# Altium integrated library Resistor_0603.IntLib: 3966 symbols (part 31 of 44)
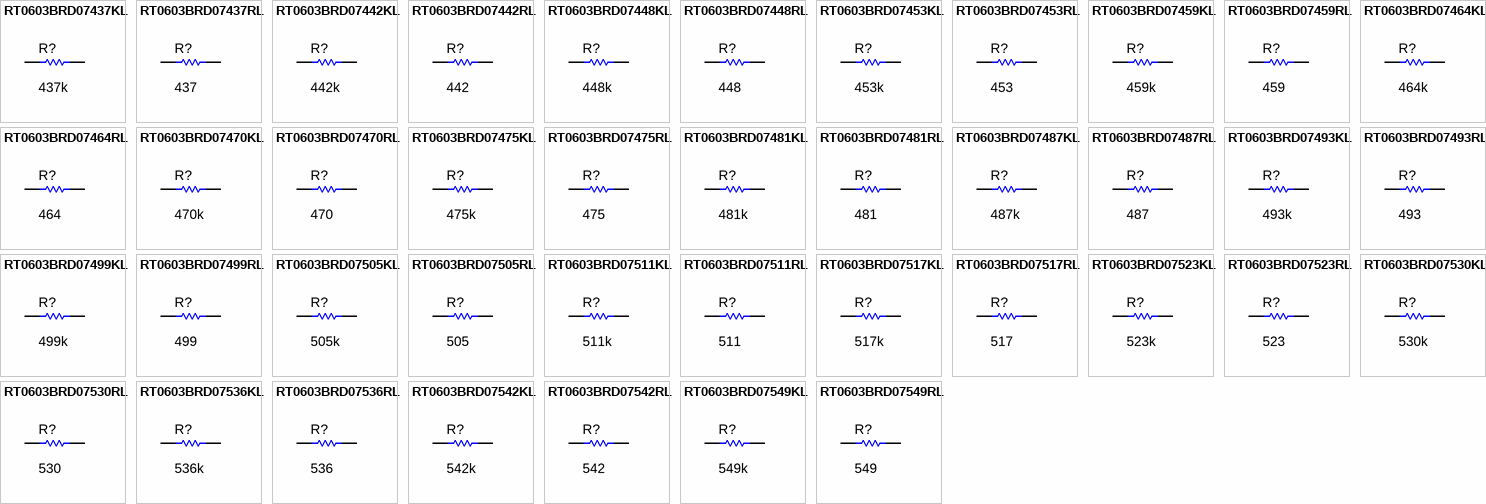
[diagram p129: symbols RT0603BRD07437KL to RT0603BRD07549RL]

## RT0603BRD07487KL
designator R?  ValueDisplayed: 487k  (hidden comment: RT0603BRD07487KL)
RES, 487 k, 0.1%, 0.1 W, 0603; Manufacturer: Yageo America; CompType: Resistor; Value: 487k; Res_ohm: 487000; Tolerance_%: 0.1; Value2: 0.1W; VDC_V: 75; TempCo: 25 ppm/C; SizeArea_mm2: 1.28; SizeX_mm: 1.6; SizeY_mm: 0.8; SizeZ_mm: 1; EIA_Code: E192; U/M: EA; AEC Category: Q200
signal-integrity model Resistor
simulation model Resistor
footprint 0603
footprint 0603M
footprint 0603L
footprint 0603_HV
footprint 0603S
pins: 1, 2

## RT0603BRD07487RL
designator R?  ValueDisplayed: 487  (hidden comment: RT0603BRD07487RL)
RES, 487, 0.1%, 0.1 W, 0603; Manufacturer: Yageo America; CompType: Resistor; Value: 487; Value_Code: 487R; Tolerance_%: 0.1; Value2: 0.1W; VDC_V: 75; TempCo: 25 ppm/C; SizeArea_mm2: 1.28; SizeX_mm: 1.6; SizeY_mm: 0.8; SizeZ_mm: 1; EIA_Code: E192; U/M: EA; AEC Category: Q200
signal-integrity model Resistor
simulation model Resistor
footprint 0603
footprint 0603M
footprint 0603L
footprint 0603_HV
footprint 0603S
pins: 1, 2

## RT0603BRD07493KL
designator R?  ValueDisplayed: 493k  (hidden comment: RT0603BRD07493KL)
RES, 493 k, 0.1%, 0.1 W, 0603; Manufacturer: Yageo America; CompType: Resistor; Value: 493k; Res_ohm: 493000; Tolerance_%: 0.1; Value2: 0.1W; VDC_V: 75; TempCo: 25 ppm/C; SizeArea_mm2: 1.28; SizeX_mm: 1.6; SizeY_mm: 0.8; SizeZ_mm: 1; EIA_Code: E192; U/M: EA; AEC Category: Q200
signal-integrity model Resistor
simulation model Resistor
footprint 0603
footprint 0603M
footprint 0603L
footprint 0603_HV
footprint 0603S
pins: 1, 2

## RT0603BRD07493RL
designator R?  ValueDisplayed: 493  (hidden comment: RT0603BRD07493RL)
RES, 493, 0.1%, 0.1 W, 0603; Manufacturer: Yageo America; CompType: Resistor; Value: 493; Value_Code: 493R; Tolerance_%: 0.1; Value2: 0.1W; VDC_V: 75; TempCo: 25 ppm/C; SizeArea_mm2: 1.28; SizeX_mm: 1.6; SizeY_mm: 0.8; SizeZ_mm: 1; EIA_Code: E192; U/M: EA; AEC Category: Q200
signal-integrity model Resistor
simulation model Resistor
footprint 0603
footprint 0603M
footprint 0603L
footprint 0603_HV
footprint 0603S
pins: 1, 2

## RT0603BRD07499KL
designator R?  ValueDisplayed: 499k  (hidden comment: RT0603BRD07499KL)
RES, 499 k, 0.1%, 0.1 W, 0603; Manufacturer: Yageo America; CompType: Resistor; Value: 499k; Res_ohm: 499000; Tolerance_%: 0.1; Value2: 0.1W; VDC_V: 75; TempCo: 25 ppm/C; SizeArea_mm2: 1.28; SizeX_mm: 1.6; SizeY_mm: 0.8; SizeZ_mm: 1; EIA_Code: E192; U/M: EA; AEC Category: Q200; Green_Lifecycle: Active; Green_REACh: Passed
signal-integrity model Resistor
simulation model Resistor
footprint 0603
footprint 0603M
footprint 0603L
footprint 0603_HV
footprint 0603S
pins: 1, 2

## RT0603BRD07499RL
designator R?  ValueDisplayed: 499  (hidden comment: RT0603BRD07499RL)
RES, 499, 0.1%, 0.1 W, 0603; Manufacturer: Yageo America; CompType: Resistor; Value: 499; Value_Code: 499R; Tolerance_%: 0.1; Value2: 0.1W; VDC_V: 75; TempCo: 25 ppm/C; SizeArea_mm2: 1.28; SizeX_mm: 1.6; SizeY_mm: 0.8; SizeZ_mm: 1; EIA_Code: E192; U/M: EA; AEC Category: Q200
signal-integrity model Resistor
simulation model Resistor
footprint 0603
footprint 0603M
footprint 0603L
footprint 0603_HV
footprint 0603S
pins: 1, 2

## RT0603BRD07505KL
designator R?  ValueDisplayed: 505k  (hidden comment: RT0603BRD07505KL)
RES, 505 k, 0.1%, 0.1 W, 0603; Manufacturer: Yageo America; CompType: Resistor; Value: 505k; Res_ohm: 505000; Tolerance_%: 0.1; Value2: 0.1W; VDC_V: 75; TempCo: 25 ppm/C; SizeArea_mm2: 1.28; SizeX_mm: 1.6; SizeY_mm: 0.8; SizeZ_mm: 1; EIA_Code: E192; U/M: EA; AEC Category: Q200
signal-integrity model Resistor
simulation model Resistor
footprint 0603
footprint 0603M
footprint 0603L
footprint 0603_HV
footprint 0603S
pins: 1, 2

## RT0603BRD07505RL
designator R?  ValueDisplayed: 505  (hidden comment: RT0603BRD07505RL)
RES, 505, 0.1%, 0.1 W, 0603; Manufacturer: Yageo America; CompType: Resistor; Value: 505; Value_Code: 505R; Tolerance_%: 0.1; Value2: 0.1W; VDC_V: 75; TempCo: 25 ppm/C; SizeArea_mm2: 1.28; SizeX_mm: 1.6; SizeY_mm: 0.8; SizeZ_mm: 1; EIA_Code: E192; U/M: EA; AEC Category: Q200
signal-integrity model Resistor
simulation model Resistor
footprint 0603
footprint 0603M
footprint 0603L
footprint 0603_HV
footprint 0603S
pins: 1, 2

## RT0603BRD07511KL
designator R?  ValueDisplayed: 511k  (hidden comment: RT0603BRD07511KL)
RES, 511 k, 0.1%, 0.1 W, 0603; Manufacturer: Yageo America; CompType: Resistor; Value: 511k; Res_ohm: 511000; Tolerance_%: 0.1; Value2: 0.1W; VDC_V: 75; TempCo: 25 ppm/C; SizeArea_mm2: 1.28; SizeX_mm: 1.6; SizeY_mm: 0.8; SizeZ_mm: 1; EIA_Code: E192; U/M: EA; AEC Category: Q200
signal-integrity model Resistor
simulation model Resistor
footprint 0603
footprint 0603M
footprint 0603L
footprint 0603_HV
footprint 0603S
pins: 1, 2

## RT0603BRD07511RL
designator R?  ValueDisplayed: 511  (hidden comment: RT0603BRD07511RL)
RES, 511, 0.1%, 0.1 W, 0603; Manufacturer: Yageo America; CompType: Resistor; Value: 511; Value_Code: 511R; Tolerance_%: 0.1; Value2: 0.1W; VDC_V: 75; TempCo: 25 ppm/C; SizeArea_mm2: 1.28; SizeX_mm: 1.6; SizeY_mm: 0.8; SizeZ_mm: 1; EIA_Code: E192; U/M: EA; AEC Category: Q200
signal-integrity model Resistor
simulation model Resistor
footprint 0603
footprint 0603M
footprint 0603L
footprint 0603_HV
footprint 0603S
pins: 1, 2

## RT0603BRD07517KL
designator R?  ValueDisplayed: 517k  (hidden comment: RT0603BRD07517KL)
RES, 517 k, 0.1%, 0.1 W, 0603; Manufacturer: Yageo America; CompType: Resistor; Value: 517k; Res_ohm: 517000; Tolerance_%: 0.1; Value2: 0.1W; VDC_V: 75; TempCo: 25 ppm/C; SizeArea_mm2: 1.28; SizeX_mm: 1.6; SizeY_mm: 0.8; SizeZ_mm: 1; EIA_Code: E192; U/M: EA; AEC Category: Q200
signal-integrity model Resistor
simulation model Resistor
footprint 0603
footprint 0603M
footprint 0603L
footprint 0603_HV
footprint 0603S
pins: 1, 2

## RT0603BRD07517RL
designator R?  ValueDisplayed: 517  (hidden comment: RT0603BRD07517RL)
RES, 517, 0.1%, 0.1 W, 0603; Manufacturer: Yageo America; CompType: Resistor; Value: 517; Value_Code: 517R; Tolerance_%: 0.1; Value2: 0.1W; VDC_V: 75; TempCo: 25 ppm/C; SizeArea_mm2: 1.28; SizeX_mm: 1.6; SizeY_mm: 0.8; SizeZ_mm: 1; EIA_Code: E192; U/M: EA; AEC Category: Q200
signal-integrity model Resistor
simulation model Resistor
footprint 0603
footprint 0603M
footprint 0603L
footprint 0603_HV
footprint 0603S
pins: 1, 2

## RT0603BRD07523KL
designator R?  ValueDisplayed: 523k  (hidden comment: RT0603BRD07523KL)
RES, 523 k, 0.1%, 0.1 W, 0603; Manufacturer: Yageo America; CompType: Resistor; Value: 523k; Res_ohm: 523000; Tolerance_%: 0.1; Value2: 0.1W; VDC_V: 75; TempCo: 25 ppm/C; SizeArea_mm2: 1.28; SizeX_mm: 1.6; SizeY_mm: 0.8; SizeZ_mm: 1; EIA_Code: E192; U/M: EA; AEC Category: Q200
signal-integrity model Resistor
simulation model Resistor
footprint 0603
footprint 0603M
footprint 0603L
footprint 0603_HV
footprint 0603S
pins: 1, 2

## RT0603BRD07523RL
designator R?  ValueDisplayed: 523  (hidden comment: RT0603BRD07523RL)
RES, 523, 0.1%, 0.1 W, 0603; Manufacturer: Yageo America; CompType: Resistor; Value: 523; Value_Code: 523R; Tolerance_%: 0.1; Value2: 0.1W; VDC_V: 75; TempCo: 25 ppm/C; SizeArea_mm2: 1.28; SizeX_mm: 1.6; SizeY_mm: 0.8; SizeZ_mm: 1; EIA_Code: E192; U/M: EA; AEC Category: Q200
signal-integrity model Resistor
simulation model Resistor
footprint 0603
footprint 0603M
footprint 0603L
footprint 0603_HV
footprint 0603S
pins: 1, 2

## RT0603BRD07530KL
designator R?  ValueDisplayed: 530k  (hidden comment: RT0603BRD07530KL)
RES, 530 k, 0.1%, 0.1 W, 0603; Manufacturer: Yageo America; CompType: Resistor; Value: 530k; Res_ohm: 530000; Tolerance_%: 0.1; Value2: 0.1W; VDC_V: 75; TempCo: 25 ppm/C; SizeArea_mm2: 1.28; SizeX_mm: 1.6; SizeY_mm: 0.8; SizeZ_mm: 1; EIA_Code: E192; U/M: EA; AEC Category: Q200
signal-integrity model Resistor
simulation model Resistor
footprint 0603
footprint 0603M
footprint 0603L
footprint 0603_HV
footprint 0603S
pins: 1, 2

## RT0603BRD07530RL
designator R?  ValueDisplayed: 530  (hidden comment: RT0603BRD07530RL)
RES, 530, 0.1%, 0.1 W, 0603; Manufacturer: Yageo America; CompType: Resistor; Value: 530; Value_Code: 530R; Tolerance_%: 0.1; Value2: 0.1W; VDC_V: 75; TempCo: 25 ppm/C; SizeArea_mm2: 1.28; SizeX_mm: 1.6; SizeY_mm: 0.8; SizeZ_mm: 1; EIA_Code: E192; U/M: EA; AEC Category: Q200
signal-integrity model Resistor
simulation model Resistor
footprint 0603
footprint 0603M
footprint 0603L
footprint 0603_HV
footprint 0603S
pins: 1, 2

## RT0603BRD07536KL
designator R?  ValueDisplayed: 536k  (hidden comment: RT0603BRD07536KL)
RES, 536 k, 0.1%, 0.1 W, 0603; Manufacturer: Yageo America; CompType: Resistor; Value: 536k; Res_ohm: 536000; Tolerance_%: 0.1; Value2: 0.1W; VDC_V: 75; TempCo: 25 ppm/C; SizeArea_mm2: 1.28; SizeX_mm: 1.6; SizeY_mm: 0.8; SizeZ_mm: 1; EIA_Code: E192; U/M: EA; AEC Category: Q200
signal-integrity model Resistor
simulation model Resistor
footprint 0603
footprint 0603M
footprint 0603L
footprint 0603_HV
footprint 0603S
pins: 1, 2

## RT0603BRD07536RL
designator R?  ValueDisplayed: 536  (hidden comment: RT0603BRD07536RL)
RES, 536, 0.1%, 0.1 W, 0603; Manufacturer: Yageo America; CompType: Resistor; Value: 536; Value_Code: 536R; Tolerance_%: 0.1; Value2: 0.1W; VDC_V: 75; TempCo: 25 ppm/C; SizeArea_mm2: 1.28; SizeX_mm: 1.6; SizeY_mm: 0.8; SizeZ_mm: 1; EIA_Code: E192; U/M: EA; AEC Category: Q200
signal-integrity model Resistor
simulation model Resistor
footprint 0603
footprint 0603M
footprint 0603L
footprint 0603_HV
footprint 0603S
pins: 1, 2

## RT0603BRD07542KL
designator R?  ValueDisplayed: 542k  (hidden comment: RT0603BRD07542KL)
RES, 542 k, 0.1%, 0.1 W, 0603; Manufacturer: Yageo America; CompType: Resistor; Value: 542k; Res_ohm: 542000; Tolerance_%: 0.1; Value2: 0.1W; VDC_V: 75; TempCo: 25 ppm/C; SizeArea_mm2: 1.28; SizeX_mm: 1.6; SizeY_mm: 0.8; SizeZ_mm: 1; EIA_Code: E192; U/M: EA; AEC Category: Q200
signal-integrity model Resistor
simulation model Resistor
footprint 0603
footprint 0603M
footprint 0603L
footprint 0603_HV
footprint 0603S
pins: 1, 2

## RT0603BRD07542RL
designator R?  ValueDisplayed: 542  (hidden comment: RT0603BRD07542RL)
RES, 542, 0.1%, 0.1 W, 0603; Manufacturer: Yageo America; CompType: Resistor; Value: 542; Value_Code: 542R; Tolerance_%: 0.1; Value2: 0.1W; VDC_V: 75; TempCo: 25 ppm/C; SizeArea_mm2: 1.28; SizeX_mm: 1.6; SizeY_mm: 0.8; SizeZ_mm: 1; EIA_Code: E192; U/M: EA; AEC Category: Q200
signal-integrity model Resistor
simulation model Resistor
footprint 0603
footprint 0603M
footprint 0603L
footprint 0603_HV
footprint 0603S
pins: 1, 2

## RT0603BRD07549KL
designator R?  ValueDisplayed: 549k  (hidden comment: RT0603BRD07549KL)
RES, 549 k, 0.1%, 0.1 W, 0603; Manufacturer: Yageo America; CompType: Resistor; Value: 549k; Res_ohm: 549000; Tolerance_%: 0.1; Value2: 0.1W; VDC_V: 75; TempCo: 25 ppm/C; SizeArea_mm2: 1.28; SizeX_mm: 1.6; SizeY_mm: 0.8; SizeZ_mm: 1; EIA_Code: E192; U/M: EA; AEC Category: Q200
signal-integrity model Resistor
simulation model Resistor
footprint 0603
footprint 0603M
footprint 0603L
footprint 0603_HV
footprint 0603S
pins: 1, 2

## RT0603BRD07549RL
designator R?  ValueDisplayed: 549  (hidden comment: RT0603BRD07549RL)
RES, 549, 0.1%, 0.1 W, 0603; Manufacturer: Yageo America; CompType: Resistor; Value: 549; Value_Code: 549R; Tolerance_%: 0.1; Value2: 0.1W; VDC_V: 75; TempCo: 25 ppm/C; SizeArea_mm2: 1.28; SizeX_mm: 1.6; SizeY_mm: 0.8; SizeZ_mm: 1; EIA_Code: E192; U/M: EA; AEC Category: Q200
signal-integrity model Resistor
simulation model Resistor
footprint 0603
footprint 0603M
footprint 0603L
footprint 0603_HV
footprint 0603S
pins: 1, 2

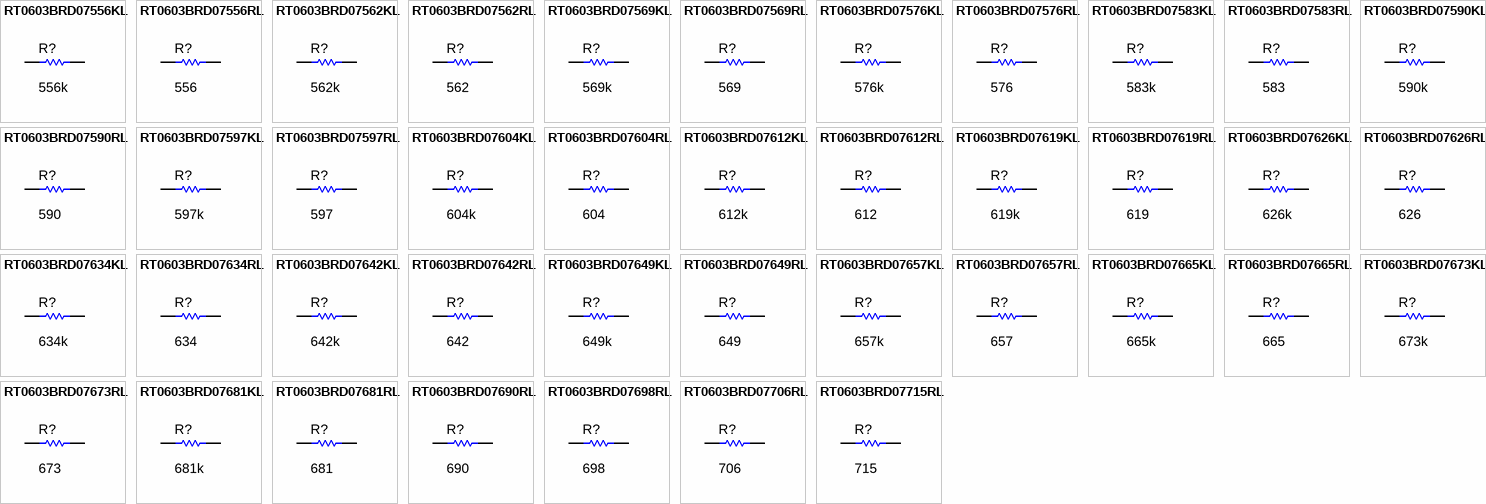
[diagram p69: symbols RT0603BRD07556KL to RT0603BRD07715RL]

## RT0603BRD07556KL
designator R?  ValueDisplayed: 556k  (hidden comment: RT0603BRD07556KL)
RES, 556 k, 0.1%, 0.1 W, 0603; Manufacturer: Yageo America; CompType: Resistor; Value: 556k; Res_ohm: 556000; Tolerance_%: 0.1; Value2: 0.1W; VDC_V: 75; TempCo: 25 ppm/C; SizeArea_mm2: 1.28; SizeX_mm: 1.6; SizeY_mm: 0.8; SizeZ_mm: 1; EIA_Code: E192; U/M: EA; AEC Category: Q200
signal-integrity model Resistor
simulation model Resistor
footprint 0603
footprint 0603M
footprint 0603L
footprint 0603_HV
footprint 0603S
pins: 1, 2

## RT0603BRD07556RL
designator R?  ValueDisplayed: 556  (hidden comment: RT0603BRD07556RL)
RES, 556, 0.1%, 0.1 W, 0603; Manufacturer: Yageo America; CompType: Resistor; Value: 556; Value_Code: 556R; Tolerance_%: 0.1; Value2: 0.1W; VDC_V: 75; TempCo: 25 ppm/C; SizeArea_mm2: 1.28; SizeX_mm: 1.6; SizeY_mm: 0.8; SizeZ_mm: 1; EIA_Code: E192; U/M: EA; AEC Category: Q200
signal-integrity model Resistor
simulation model Resistor
footprint 0603
footprint 0603M
footprint 0603L
footprint 0603_HV
footprint 0603S
pins: 1, 2

## RT0603BRD07562KL
designator R?  ValueDisplayed: 562k  (hidden comment: RT0603BRD07562KL)
RES, 562 k, 0.1%, 0.1 W, 0603; Manufacturer: Yageo America; CompType: Resistor; Value: 562k; Res_ohm: 562000; Tolerance_%: 0.1; Value2: 0.1W; VDC_V: 75; TempCo: 25 ppm/C; SizeArea_mm2: 1.28; SizeX_mm: 1.6; SizeY_mm: 0.8; SizeZ_mm: 1; EIA_Code: E192; U/M: EA; AEC Category: Q200
signal-integrity model Resistor
simulation model Resistor
footprint 0603
footprint 0603M
footprint 0603L
footprint 0603_HV
footprint 0603S
pins: 1, 2

## RT0603BRD07562RL
designator R?  ValueDisplayed: 562  (hidden comment: RT0603BRD07562RL)
RES, 562, 0.1%, 0.1 W, 0603; Manufacturer: Yageo America; CompType: Resistor; Value: 562; Value_Code: 562R; Tolerance_%: 0.1; Value2: 0.1W; VDC_V: 75; TempCo: 25 ppm/C; SizeArea_mm2: 1.28; SizeX_mm: 1.6; SizeY_mm: 0.8; SizeZ_mm: 1; EIA_Code: E192; U/M: EA; AEC Category: Q200
signal-integrity model Resistor
simulation model Resistor
footprint 0603
footprint 0603M
footprint 0603L
footprint 0603_HV
footprint 0603S
pins: 1, 2

## RT0603BRD07569KL
designator R?  ValueDisplayed: 569k  (hidden comment: RT0603BRD07569KL)
RES, 569 k, 0.1%, 0.1 W, 0603; Manufacturer: Yageo America; CompType: Resistor; Value: 569k; Res_ohm: 569000; Tolerance_%: 0.1; Value2: 0.1W; VDC_V: 75; TempCo: 25 ppm/C; SizeArea_mm2: 1.28; SizeX_mm: 1.6; SizeY_mm: 0.8; SizeZ_mm: 1; EIA_Code: E192; U/M: EA; AEC Category: Q200
signal-integrity model Resistor
simulation model Resistor
footprint 0603
footprint 0603M
footprint 0603L
footprint 0603_HV
footprint 0603S
pins: 1, 2

## RT0603BRD07569RL
designator R?  ValueDisplayed: 569  (hidden comment: RT0603BRD07569RL)
RES, 569, 0.1%, 0.1 W, 0603; Manufacturer: Yageo America; CompType: Resistor; Value: 569; Value_Code: 569R; Tolerance_%: 0.1; Value2: 0.1W; VDC_V: 75; TempCo: 25 ppm/C; SizeArea_mm2: 1.28; SizeX_mm: 1.6; SizeY_mm: 0.8; SizeZ_mm: 1; EIA_Code: E192; U/M: EA; AEC Category: Q200
signal-integrity model Resistor
simulation model Resistor
footprint 0603
footprint 0603M
footprint 0603L
footprint 0603_HV
footprint 0603S
pins: 1, 2

## RT0603BRD07576KL
designator R?  ValueDisplayed: 576k  (hidden comment: RT0603BRD07576KL)
RES, 576 k, 0.1%, 0.1 W, 0603; Manufacturer: Yageo America; CompType: Resistor; Value: 576k; Res_ohm: 576000; Tolerance_%: 0.1; Value2: 0.1W; VDC_V: 75; TempCo: 25 ppm/C; SizeArea_mm2: 1.28; SizeX_mm: 1.6; SizeY_mm: 0.8; SizeZ_mm: 1; EIA_Code: E192; U/M: EA; AEC Category: Q200
signal-integrity model Resistor
simulation model Resistor
footprint 0603
footprint 0603M
footprint 0603L
footprint 0603_HV
footprint 0603S
pins: 1, 2

## RT0603BRD07576RL
designator R?  ValueDisplayed: 576  (hidden comment: RT0603BRD07576RL)
RES, 576, 0.1%, 0.1 W, 0603; Manufacturer: Yageo America; CompType: Resistor; Value: 576; Value_Code: 576R; Tolerance_%: 0.1; Value2: 0.1W; VDC_V: 75; TempCo: 25 ppm/C; SizeArea_mm2: 1.28; SizeX_mm: 1.6; SizeY_mm: 0.8; SizeZ_mm: 1; EIA_Code: E192; U/M: EA; AEC Category: Q200
signal-integrity model Resistor
simulation model Resistor
footprint 0603
footprint 0603M
footprint 0603L
footprint 0603_HV
footprint 0603S
pins: 1, 2

## RT0603BRD07583KL
designator R?  ValueDisplayed: 583k  (hidden comment: RT0603BRD07583KL)
RES, 583 k, 0.1%, 0.1 W, 0603; Manufacturer: Yageo America; CompType: Resistor; Value: 583k; Res_ohm: 583000; Tolerance_%: 0.1; Value2: 0.1W; VDC_V: 75; TempCo: 25 ppm/C; SizeArea_mm2: 1.28; SizeX_mm: 1.6; SizeY_mm: 0.8; SizeZ_mm: 1; EIA_Code: E192; U/M: EA; AEC Category: Q200
signal-integrity model Resistor
simulation model Resistor
footprint 0603
footprint 0603M
footprint 0603L
footprint 0603_HV
footprint 0603S
pins: 1, 2

## RT0603BRD07583RL
designator R?  ValueDisplayed: 583  (hidden comment: RT0603BRD07583RL)
RES, 583, 0.1%, 0.1 W, 0603; Manufacturer: Yageo America; CompType: Resistor; Value: 583; Value_Code: 583R; Tolerance_%: 0.1; Value2: 0.1W; VDC_V: 75; TempCo: 25 ppm/C; SizeArea_mm2: 1.28; SizeX_mm: 1.6; SizeY_mm: 0.8; SizeZ_mm: 1; EIA_Code: E192; U/M: EA; AEC Category: Q200
signal-integrity model Resistor
simulation model Resistor
footprint 0603
footprint 0603M
footprint 0603L
footprint 0603_HV
footprint 0603S
pins: 1, 2

## RT0603BRD07590KL
designator R?  ValueDisplayed: 590k  (hidden comment: RT0603BRD07590KL)
RES, 590 k, 0.1%, 0.1 W, 0603; Manufacturer: Yageo America; CompType: Resistor; Value: 590k; Res_ohm: 590000; Tolerance_%: 0.1; Value2: 0.1W; VDC_V: 75; TempCo: 25 ppm/C; SizeArea_mm2: 1.28; SizeX_mm: 1.6; SizeY_mm: 0.8; SizeZ_mm: 1; EIA_Code: E192; U/M: EA; AEC Category: Q200
signal-integrity model Resistor
simulation model Resistor
footprint 0603
footprint 0603M
footprint 0603L
footprint 0603_HV
footprint 0603S
pins: 1, 2

## RT0603BRD07590RL
designator R?  ValueDisplayed: 590  (hidden comment: RT0603BRD07590RL)
RES, 590, 0.1%, 0.1 W, 0603; Manufacturer: Yageo America; CompType: Resistor; Value: 590; Value_Code: 590R; Tolerance_%: 0.1; Value2: 0.1W; VDC_V: 75; TempCo: 25 ppm/C; SizeArea_mm2: 1.28; SizeX_mm: 1.6; SizeY_mm: 0.8; SizeZ_mm: 1; EIA_Code: E192; U/M: EA; AEC Category: Q200
signal-integrity model Resistor
simulation model Resistor
footprint 0603
footprint 0603M
footprint 0603L
footprint 0603_HV
footprint 0603S
pins: 1, 2

## RT0603BRD07597KL
designator R?  ValueDisplayed: 597k  (hidden comment: RT0603BRD07597KL)
RES, 597 k, 0.1%, 0.1 W, 0603; Manufacturer: Yageo America; CompType: Resistor; Value: 597k; Res_ohm: 597000; Tolerance_%: 0.1; Value2: 0.1W; VDC_V: 75; TempCo: 25 ppm/C; SizeArea_mm2: 1.28; SizeX_mm: 1.6; SizeY_mm: 0.8; SizeZ_mm: 1; EIA_Code: E192; U/M: EA; AEC Category: Q200
signal-integrity model Resistor
simulation model Resistor
footprint 0603
footprint 0603M
footprint 0603L
footprint 0603_HV
footprint 0603S
pins: 1, 2

## RT0603BRD07597RL
designator R?  ValueDisplayed: 597  (hidden comment: RT0603BRD07597RL)
RES, 597, 0.1%, 0.1 W, 0603; Manufacturer: Yageo America; CompType: Resistor; Value: 597; Value_Code: 597R; Tolerance_%: 0.1; Value2: 0.1W; VDC_V: 75; TempCo: 25 ppm/C; SizeArea_mm2: 1.28; SizeX_mm: 1.6; SizeY_mm: 0.8; SizeZ_mm: 1; EIA_Code: E192; U/M: EA; AEC Category: Q200
signal-integrity model Resistor
simulation model Resistor
footprint 0603
footprint 0603M
footprint 0603L
footprint 0603_HV
footprint 0603S
pins: 1, 2

## RT0603BRD07604KL
designator R?  ValueDisplayed: 604k  (hidden comment: RT0603BRD07604KL)
RES, 604 k, 0.1%, 0.1 W, 0603; Manufacturer: Yageo America; CompType: Resistor; Value: 604k; Res_ohm: 604000; Tolerance_%: 0.1; Value2: 0.1W; VDC_V: 75; TempCo: 25 ppm/C; SizeArea_mm2: 1.28; SizeX_mm: 1.6; SizeY_mm: 0.8; SizeZ_mm: 1; EIA_Code: E192; U/M: EA; AEC Category: Q200
signal-integrity model Resistor
simulation model Resistor
footprint 0603
footprint 0603M
footprint 0603L
footprint 0603_HV
footprint 0603S
pins: 1, 2

## RT0603BRD07604RL
designator R?  ValueDisplayed: 604  (hidden comment: RT0603BRD07604RL)
RES, 604, 0.1%, 0.1 W, 0603; Manufacturer: Yageo America; CompType: Resistor; Value: 604; Value_Code: 604R; Tolerance_%: 0.1; Value2: 0.1W; VDC_V: 75; TempCo: 25 ppm/C; SizeArea_mm2: 1.28; SizeX_mm: 1.6; SizeY_mm: 0.8; SizeZ_mm: 1; EIA_Code: E192; U/M: EA; AEC Category: Q200
signal-integrity model Resistor
simulation model Resistor
footprint 0603
footprint 0603M
footprint 0603L
footprint 0603_HV
footprint 0603S
pins: 1, 2

## RT0603BRD07612KL
designator R?  ValueDisplayed: 612k  (hidden comment: RT0603BRD07612KL)
RES, 612 k, 0.1%, 0.1 W, 0603; Manufacturer: Yageo America; CompType: Resistor; Value: 612k; Res_ohm: 612000; Tolerance_%: 0.1; Value2: 0.1W; VDC_V: 75; TempCo: 25 ppm/C; SizeArea_mm2: 1.28; SizeX_mm: 1.6; SizeY_mm: 0.8; SizeZ_mm: 1; EIA_Code: E192; U/M: EA; AEC Category: Q200
signal-integrity model Resistor
simulation model Resistor
footprint 0603
footprint 0603M
footprint 0603L
footprint 0603_HV
footprint 0603S
pins: 1, 2

## RT0603BRD07612RL
designator R?  ValueDisplayed: 612  (hidden comment: RT0603BRD07612RL)
RES, 612, 0.1%, 0.1 W, 0603; Manufacturer: Yageo America; CompType: Resistor; Value: 612; Value_Code: 612R; Tolerance_%: 0.1; Value2: 0.1W; VDC_V: 75; TempCo: 25 ppm/C; SizeArea_mm2: 1.28; SizeX_mm: 1.6; SizeY_mm: 0.8; SizeZ_mm: 1; EIA_Code: E192; U/M: EA; AEC Category: Q200
signal-integrity model Resistor
simulation model Resistor
footprint 0603
footprint 0603M
footprint 0603L
footprint 0603_HV
footprint 0603S
pins: 1, 2

## RT0603BRD07619KL
designator R?  ValueDisplayed: 619k  (hidden comment: RT0603BRD07619KL)
RES, 619 k, 0.1%, 0.1 W, 0603; Manufacturer: Yageo America; CompType: Resistor; Value: 619k; Res_ohm: 619000; Tolerance_%: 0.1; Value2: 0.1W; VDC_V: 75; TempCo: 25 ppm/C; SizeArea_mm2: 1.28; SizeX_mm: 1.6; SizeY_mm: 0.8; SizeZ_mm: 1; EIA_Code: E192; U/M: EA; AEC Category: Q200
signal-integrity model Resistor
simulation model Resistor
footprint 0603
footprint 0603M
footprint 0603L
footprint 0603_HV
footprint 0603S
pins: 1, 2

## RT0603BRD07619RL
designator R?  ValueDisplayed: 619  (hidden comment: RT0603BRD07619RL)
RES, 619, 0.1%, 0.1 W, 0603; Manufacturer: Yageo America; CompType: Resistor; Value: 619; Value_Code: 619R; Tolerance_%: 0.1; Value2: 0.1W; VDC_V: 75; TempCo: 25 ppm/C; SizeArea_mm2: 1.28; SizeX_mm: 1.6; SizeY_mm: 0.8; SizeZ_mm: 1; EIA_Code: E192; U/M: EA; AEC Category: Q200
signal-integrity model Resistor
simulation model Resistor
footprint 0603
footprint 0603M
footprint 0603L
footprint 0603_HV
footprint 0603S
pins: 1, 2

## RT0603BRD07626KL
designator R?  ValueDisplayed: 626k  (hidden comment: RT0603BRD07626KL)
RES, 626 k, 0.1%, 0.1 W, 0603; Manufacturer: Yageo America; CompType: Resistor; Value: 626k; Res_ohm: 626000; Tolerance_%: 0.1; Value2: 0.1W; VDC_V: 75; TempCo: 25 ppm/C; SizeArea_mm2: 1.28; SizeX_mm: 1.6; SizeY_mm: 0.8; SizeZ_mm: 1; EIA_Code: E192; U/M: EA; AEC Category: Q200
signal-integrity model Resistor
simulation model Resistor
footprint 0603
footprint 0603M
footprint 0603L
footprint 0603_HV
footprint 0603S
pins: 1, 2

## RT0603BRD07626RL
designator R?  ValueDisplayed: 626  (hidden comment: RT0603BRD07626RL)
RES, 626, 0.1%, 0.1 W, 0603; Manufacturer: Yageo America; CompType: Resistor; Value: 626; Value_Code: 626R; Tolerance_%: 0.1; Value2: 0.1W; VDC_V: 75; TempCo: 25 ppm/C; SizeArea_mm2: 1.28; SizeX_mm: 1.6; SizeY_mm: 0.8; SizeZ_mm: 1; EIA_Code: E192; U/M: EA; AEC Category: Q200
signal-integrity model Resistor
simulation model Resistor
footprint 0603
footprint 0603M
footprint 0603L
footprint 0603_HV
footprint 0603S
pins: 1, 2

## RT0603BRD07634KL
designator R?  ValueDisplayed: 634k  (hidden comment: RT0603BRD07634KL)
RES, 634 k, 0.1%, 0.1 W, 0603; Manufacturer: Yageo America; CompType: Resistor; Value: 634k; Res_ohm: 634000; Tolerance_%: 0.1; Value2: 0.1W; VDC_V: 75; TempCo: 25 ppm/C; SizeArea_mm2: 1.28; SizeX_mm: 1.6; SizeY_mm: 0.8; SizeZ_mm: 1; EIA_Code: E192; U/M: EA; AEC Category: Q200
signal-integrity model Resistor
simulation model Resistor
footprint 0603
footprint 0603M
footprint 0603L
footprint 0603_HV
footprint 0603S
pins: 1, 2

## RT0603BRD07634RL
designator R?  ValueDisplayed: 634  (hidden comment: RT0603BRD07634RL)
RES, 634, 0.1%, 0.1 W, 0603; Manufacturer: Yageo America; CompType: Resistor; Value: 634; Value_Code: 634R; Tolerance_%: 0.1; Value2: 0.1W; VDC_V: 75; TempCo: 25 ppm/C; SizeArea_mm2: 1.28; SizeX_mm: 1.6; SizeY_mm: 0.8; SizeZ_mm: 1; EIA_Code: E192; U/M: EA; AEC Category: Q200
signal-integrity model Resistor
simulation model Resistor
footprint 0603
footprint 0603M
footprint 0603L
footprint 0603_HV
footprint 0603S
pins: 1, 2

## RT0603BRD07642KL
designator R?  ValueDisplayed: 642k  (hidden comment: RT0603BRD07642KL)
RES, 642 k, 0.1%, 0.1 W, 0603; Manufacturer: Yageo America; CompType: Resistor; Value: 642k; Res_ohm: 642000; Tolerance_%: 0.1; Value2: 0.1W; VDC_V: 75; TempCo: 25 ppm/C; SizeArea_mm2: 1.28; SizeX_mm: 1.6; SizeY_mm: 0.8; SizeZ_mm: 1; EIA_Code: E192; U/M: EA; AEC Category: Q200
signal-integrity model Resistor
simulation model Resistor
footprint 0603
footprint 0603M
footprint 0603L
footprint 0603_HV
footprint 0603S
pins: 1, 2

## RT0603BRD07642RL
designator R?  ValueDisplayed: 642  (hidden comment: RT0603BRD07642RL)
RES, 642, 0.1%, 0.1 W, 0603; Manufacturer: Yageo America; CompType: Resistor; Value: 642; Value_Code: 642R; Tolerance_%: 0.1; Value2: 0.1W; VDC_V: 75; TempCo: 25 ppm/C; SizeArea_mm2: 1.28; SizeX_mm: 1.6; SizeY_mm: 0.8; SizeZ_mm: 1; EIA_Code: E192; U/M: EA; AEC Category: Q200
signal-integrity model Resistor
simulation model Resistor
footprint 0603
footprint 0603M
footprint 0603L
footprint 0603_HV
footprint 0603S
pins: 1, 2

## RT0603BRD07649KL
designator R?  ValueDisplayed: 649k  (hidden comment: RT0603BRD07649KL)
RES, 649 k, 0.1%, 0.1 W, 0603; Manufacturer: Yageo America; CompType: Resistor; Value: 649k; Res_ohm: 649000; Tolerance_%: 0.1; Value2: 0.1W; VDC_V: 75; TempCo: 25 ppm/C; SizeArea_mm2: 1.28; SizeX_mm: 1.6; SizeY_mm: 0.8; SizeZ_mm: 1; EIA_Code: E192; U/M: EA; AEC Category: Q200
signal-integrity model Resistor
simulation model Resistor
footprint 0603
footprint 0603M
footprint 0603L
footprint 0603_HV
footprint 0603S
pins: 1, 2

## RT0603BRD07649RL
designator R?  ValueDisplayed: 649  (hidden comment: RT0603BRD07649RL)
RES, 649, 0.1%, 0.1 W, 0603; Manufacturer: Yageo America; CompType: Resistor; Value: 649; Value_Code: 649R; Tolerance_%: 0.1; Value2: 0.1W; VDC_V: 75; TempCo: 25 ppm/C; SizeArea_mm2: 1.28; SizeX_mm: 1.6; SizeY_mm: 0.8; SizeZ_mm: 1; EIA_Code: E192; U/M: EA; AEC Category: Q200; AEC Qualified: N
signal-integrity model Resistor
simulation model Resistor
footprint 0603
footprint 0603M
footprint 0603L
footprint 0603_HV
footprint 0603S
pins: 1, 2

## RT0603BRD07657KL
designator R?  ValueDisplayed: 657k  (hidden comment: RT0603BRD07657KL)
RES, 657 k, 0.1%, 0.1 W, 0603; Manufacturer: Yageo America; CompType: Resistor; Value: 657k; Res_ohm: 657000; Tolerance_%: 0.1; Value2: 0.1W; VDC_V: 75; TempCo: 25 ppm/C; SizeArea_mm2: 1.28; SizeX_mm: 1.6; SizeY_mm: 0.8; SizeZ_mm: 1; EIA_Code: E192; U/M: EA; AEC Category: Q200
signal-integrity model Resistor
simulation model Resistor
footprint 0603
footprint 0603M
footprint 0603L
footprint 0603_HV
footprint 0603S
pins: 1, 2

## RT0603BRD07657RL
designator R?  ValueDisplayed: 657  (hidden comment: RT0603BRD07657RL)
RES, 657, 0.1%, 0.1 W, 0603; Manufacturer: Yageo America; CompType: Resistor; Value: 657; Value_Code: 657R; Tolerance_%: 0.1; Value2: 0.1W; VDC_V: 75; TempCo: 25 ppm/C; SizeArea_mm2: 1.28; SizeX_mm: 1.6; SizeY_mm: 0.8; SizeZ_mm: 1; EIA_Code: E192; U/M: EA; AEC Category: Q200
signal-integrity model Resistor
simulation model Resistor
footprint 0603
footprint 0603M
footprint 0603L
footprint 0603_HV
footprint 0603S
pins: 1, 2

## RT0603BRD07665KL
designator R?  ValueDisplayed: 665k  (hidden comment: RT0603BRD07665KL)
RES, 665 k, 0.1%, 0.1 W, 0603; Manufacturer: Yageo America; CompType: Resistor; Value: 665k; Res_ohm: 665000; Tolerance_%: 0.1; Value2: 0.1W; VDC_V: 75; TempCo: 25 ppm/C; SizeArea_mm2: 1.28; SizeX_mm: 1.6; SizeY_mm: 0.8; SizeZ_mm: 1; EIA_Code: E192; U/M: EA; AEC Category: Q200
signal-integrity model Resistor
simulation model Resistor
footprint 0603
footprint 0603M
footprint 0603L
footprint 0603_HV
footprint 0603S
pins: 1, 2

## RT0603BRD07665RL
designator R?  ValueDisplayed: 665  (hidden comment: RT0603BRD07665RL)
RES, 665, 0.1%, 0.1 W, 0603; Manufacturer: Yageo America; CompType: Resistor; Value: 665; Value_Code: 665R; Tolerance_%: 0.1; Value2: 0.1W; VDC_V: 75; TempCo: 25 ppm/C; SizeArea_mm2: 1.28; SizeX_mm: 1.6; SizeY_mm: 0.8; SizeZ_mm: 1; EIA_Code: E192; U/M: EA; AEC Category: Q200
signal-integrity model Resistor
simulation model Resistor
footprint 0603
footprint 0603M
footprint 0603L
footprint 0603_HV
footprint 0603S
pins: 1, 2

## RT0603BRD07673KL
designator R?  ValueDisplayed: 673k  (hidden comment: RT0603BRD07673KL)
RES, 673 k, 0.1%, 0.1 W, 0603; Manufacturer: Yageo America; CompType: Resistor; Value: 673k; Res_ohm: 673000; Tolerance_%: 0.1; Value2: 0.1W; VDC_V: 75; TempCo: 25 ppm/C; SizeArea_mm2: 1.28; SizeX_mm: 1.6; SizeY_mm: 0.8; SizeZ_mm: 1; EIA_Code: E192; U/M: EA; AEC Category: Q200
signal-integrity model Resistor
simulation model Resistor
footprint 0603
footprint 0603M
footprint 0603L
footprint 0603_HV
footprint 0603S
pins: 1, 2

## RT0603BRD07673RL
designator R?  ValueDisplayed: 673  (hidden comment: RT0603BRD07673RL)
RES, 673, 0.1%, 0.1 W, 0603; Manufacturer: Yageo America; CompType: Resistor; Value: 673; Value_Code: 673R; Tolerance_%: 0.1; Value2: 0.1W; VDC_V: 75; TempCo: 25 ppm/C; SizeArea_mm2: 1.28; SizeX_mm: 1.6; SizeY_mm: 0.8; SizeZ_mm: 1; EIA_Code: E192; U/M: EA; AEC Category: Q200
signal-integrity model Resistor
simulation model Resistor
footprint 0603
footprint 0603M
footprint 0603L
footprint 0603_HV
footprint 0603S
pins: 1, 2

## RT0603BRD07681KL
designator R?  ValueDisplayed: 681k  (hidden comment: RT0603BRD07681KL)
RES, 681 k, 0.1%, 0.1 W, 0603; Manufacturer: Yageo America; CompType: Resistor; Value: 681k; Res_ohm: 681000; Tolerance_%: 0.1; Value2: 0.1W; VDC_V: 75; TempCo: 25 ppm/C; SizeArea_mm2: 1.28; SizeX_mm: 1.6; SizeY_mm: 0.8; SizeZ_mm: 1; EIA_Code: E192; U/M: EA; AEC Category: Q200
signal-integrity model Resistor
simulation model Resistor
footprint 0603
footprint 0603M
footprint 0603L
footprint 0603_HV
footprint 0603S
pins: 1, 2

## RT0603BRD07681RL
designator R?  ValueDisplayed: 681  (hidden comment: RT0603BRD07681RL)
RES, 681, 0.1%, 0.1 W, 0603; Manufacturer: Yageo America; CompType: Resistor; Value: 681; Value_Code: 681R; Tolerance_%: 0.1; Value2: 0.1W; VDC_V: 75; TempCo: 25 ppm/C; SizeArea_mm2: 1.28; SizeX_mm: 1.6; SizeY_mm: 0.8; SizeZ_mm: 1; EIA_Code: E192; U/M: EA; AEC Category: Q200
signal-integrity model Resistor
simulation model Resistor
footprint 0603
footprint 0603M
footprint 0603L
footprint 0603_HV
footprint 0603S
pins: 1, 2

## RT0603BRD07690RL
designator R?  ValueDisplayed: 690  (hidden comment: RT0603BRD07690RL)
RES, 690, 0.1%, 0.1 W, 0603; Manufacturer: Yageo America; CompType: Resistor; Value: 690; Value_Code: 690R; Tolerance_%: 0.1; Value2: 0.1W; VDC_V: 75; TempCo: 25 ppm/C; SizeArea_mm2: 1.28; SizeX_mm: 1.6; SizeY_mm: 0.8; SizeZ_mm: 1; EIA_Code: E192; U/M: EA; AEC Category: Q200
signal-integrity model Resistor
simulation model Resistor
footprint 0603
footprint 0603M
footprint 0603L
footprint 0603_HV
footprint 0603S
pins: 1, 2

## RT0603BRD07698RL
designator R?  ValueDisplayed: 698  (hidden comment: RT0603BRD07698RL)
RES, 698, 0.1%, 0.1 W, 0603; Manufacturer: Yageo America; CompType: Resistor; Value: 698; Value_Code: 698R; Tolerance_%: 0.1; Value2: 0.1W; VDC_V: 75; TempCo: 25 ppm/C; SizeArea_mm2: 1.28; SizeX_mm: 1.6; SizeY_mm: 0.8; SizeZ_mm: 1; EIA_Code: E192; U/M: EA; AEC Category: Q200
signal-integrity model Resistor
simulation model Resistor
footprint 0603
footprint 0603M
footprint 0603L
footprint 0603_HV
footprint 0603S
pins: 1, 2

## RT0603BRD07706RL
designator R?  ValueDisplayed: 706  (hidden comment: RT0603BRD07706RL)
RES, 706, 0.1%, 0.1 W, 0603; Manufacturer: Yageo America; CompType: Resistor; Value: 706; Value_Code: 706R; Tolerance_%: 0.1; Value2: 0.1W; VDC_V: 75; TempCo: 25 ppm/C; SizeArea_mm2: 1.28; SizeX_mm: 1.6; SizeY_mm: 0.8; SizeZ_mm: 1; EIA_Code: E192; U/M: EA; AEC Category: Q200
signal-integrity model Resistor
simulation model Resistor
footprint 0603
footprint 0603M
footprint 0603L
footprint 0603_HV
footprint 0603S
pins: 1, 2

## RT0603BRD07715RL
designator R?  ValueDisplayed: 715  (hidden comment: RT0603BRD07715RL)
RES, 715, 0.1%, 0.1 W, 0603; Manufacturer: Yageo America; CompType: Resistor; Value: 715; Value_Code: 715R; Tolerance_%: 0.1; Value2: 0.1W; VDC_V: 75; TempCo: 25 ppm/C; SizeArea_mm2: 1.28; SizeX_mm: 1.6; SizeY_mm: 0.8; SizeZ_mm: 1; EIA_Code: E192; U/M: EA; AEC Category: Q200
signal-integrity model Resistor
simulation model Resistor
footprint 0603
footprint 0603M
footprint 0603L
footprint 0603_HV
footprint 0603S
pins: 1, 2

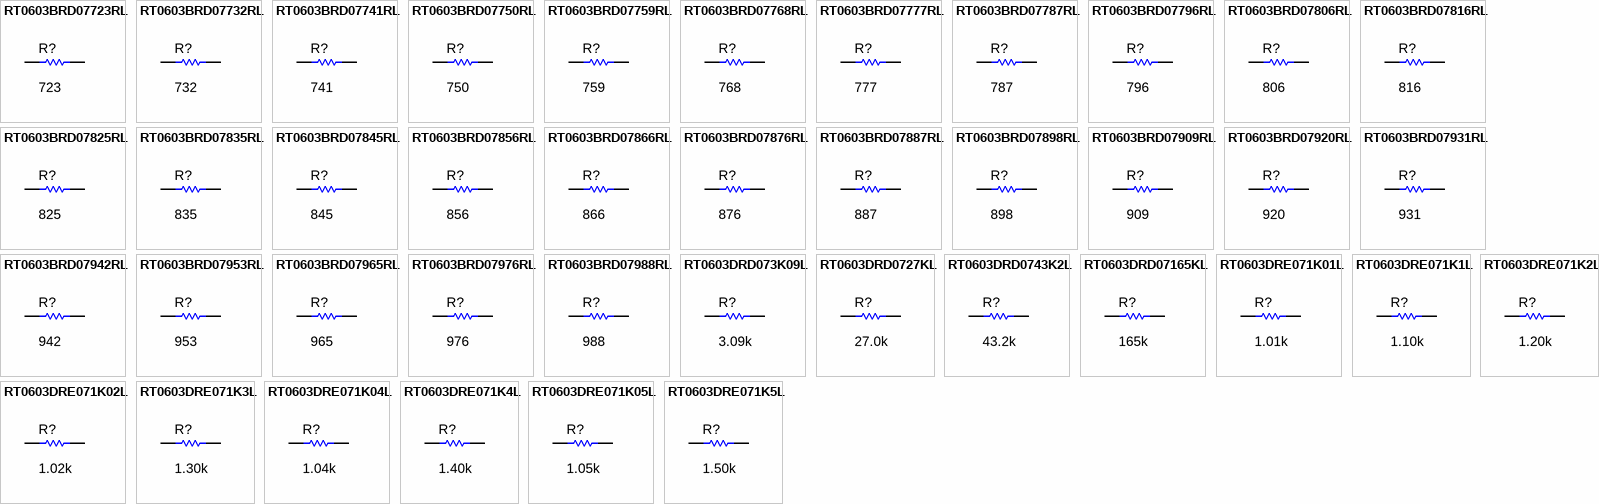
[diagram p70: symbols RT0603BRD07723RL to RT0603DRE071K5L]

## RT0603BRD07723RL
designator R?  ValueDisplayed: 723  (hidden comment: RT0603BRD07723RL)
RES, 723, 0.1%, 0.1 W, 0603; Manufacturer: Yageo America; CompType: Resistor; Value: 723; Value_Code: 723R; Tolerance_%: 0.1; Value2: 0.1W; VDC_V: 75; TempCo: 25 ppm/C; SizeArea_mm2: 1.28; SizeX_mm: 1.6; SizeY_mm: 0.8; SizeZ_mm: 1; EIA_Code: E192; U/M: EA; AEC Category: Q200
signal-integrity model Resistor
simulation model Resistor
footprint 0603
footprint 0603M
footprint 0603L
footprint 0603_HV
footprint 0603S
pins: 1, 2

## RT0603BRD07732RL
designator R?  ValueDisplayed: 732  (hidden comment: RT0603BRD07732RL)
RES, 732, 0.1%, 0.1 W, 0603; Manufacturer: Yageo America; CompType: Resistor; Value: 732; Value_Code: 732R; Tolerance_%: 0.1; Value2: 0.1W; VDC_V: 75; TempCo: 25 ppm/C; SizeArea_mm2: 1.28; SizeX_mm: 1.6; SizeY_mm: 0.8; SizeZ_mm: 1; EIA_Code: E192; U/M: EA; AEC Category: Q200
signal-integrity model Resistor
simulation model Resistor
footprint 0603
footprint 0603M
footprint 0603L
footprint 0603_HV
footprint 0603S
pins: 1, 2

## RT0603BRD07741RL
designator R?  ValueDisplayed: 741  (hidden comment: RT0603BRD07741RL)
RES, 741, 0.1%, 0.1 W, 0603; Manufacturer: Yageo America; CompType: Resistor; Value: 741; Value_Code: 741R; Tolerance_%: 0.1; Value2: 0.1W; VDC_V: 75; TempCo: 25 ppm/C; SizeArea_mm2: 1.28; SizeX_mm: 1.6; SizeY_mm: 0.8; SizeZ_mm: 1; EIA_Code: E192; U/M: EA; AEC Category: Q200
signal-integrity model Resistor
simulation model Resistor
footprint 0603
footprint 0603M
footprint 0603L
footprint 0603_HV
footprint 0603S
pins: 1, 2

## RT0603BRD07750RL
designator R?  ValueDisplayed: 750  (hidden comment: RT0603BRD07750RL)
RES, 750, 0.1%, 0.1 W, 0603; Manufacturer: Yageo America; CompType: Resistor; Value: 750; Value_Code: 750R; Tolerance_%: 0.1; Value2: 0.1W; VDC_V: 75; TempCo: 25 ppm/C; SizeArea_mm2: 1.28; SizeX_mm: 1.6; SizeY_mm: 0.8; SizeZ_mm: 1; EIA_Code: E192; U/M: EA; AEC Category: Q200
signal-integrity model Resistor
simulation model Resistor
footprint 0603
footprint 0603M
footprint 0603L
footprint 0603_HV
footprint 0603S
pins: 1, 2

## RT0603BRD07759RL
designator R?  ValueDisplayed: 759  (hidden comment: RT0603BRD07759RL)
RES, 759, 0.1%, 0.1 W, 0603; Manufacturer: Yageo America; CompType: Resistor; Value: 759; Value_Code: 759R; Tolerance_%: 0.1; Value2: 0.1W; VDC_V: 75; TempCo: 25 ppm/C; SizeArea_mm2: 1.28; SizeX_mm: 1.6; SizeY_mm: 0.8; SizeZ_mm: 1; EIA_Code: E192; U/M: EA; AEC Category: Q200
signal-integrity model Resistor
simulation model Resistor
footprint 0603
footprint 0603M
footprint 0603L
footprint 0603_HV
footprint 0603S
pins: 1, 2

## RT0603BRD07768RL
designator R?  ValueDisplayed: 768  (hidden comment: RT0603BRD07768RL)
RES, 768, 0.1%, 0.1 W, 0603; Manufacturer: Yageo America; CompType: Resistor; Value: 768; Value_Code: 768R; Tolerance_%: 0.1; Value2: 0.1W; VDC_V: 75; TempCo: 25 ppm/C; SizeArea_mm2: 1.28; SizeX_mm: 1.6; SizeY_mm: 0.8; SizeZ_mm: 1; EIA_Code: E192; U/M: EA; AEC Category: Q200
signal-integrity model Resistor
simulation model Resistor
footprint 0603
footprint 0603M
footprint 0603L
footprint 0603_HV
footprint 0603S
pins: 1, 2

## RT0603BRD07777RL
designator R?  ValueDisplayed: 777  (hidden comment: RT0603BRD07777RL)
RES, 777, 0.1%, 0.1 W, 0603; Manufacturer: Yageo America; CompType: Resistor; Value: 777; Value_Code: 777R; Tolerance_%: 0.1; Value2: 0.1W; VDC_V: 75; TempCo: 25 ppm/C; SizeArea_mm2: 1.28; SizeX_mm: 1.6; SizeY_mm: 0.8; SizeZ_mm: 1; EIA_Code: E192; U/M: EA; AEC Category: Q200
signal-integrity model Resistor
simulation model Resistor
footprint 0603
footprint 0603M
footprint 0603L
footprint 0603_HV
footprint 0603S
pins: 1, 2

## RT0603BRD07787RL
designator R?  ValueDisplayed: 787  (hidden comment: RT0603BRD07787RL)
RES, 787, 0.1%, 0.1 W, 0603; Manufacturer: Yageo America; CompType: Resistor; Value: 787; Value_Code: 787R; Tolerance_%: 0.1; Value2: 0.1W; VDC_V: 75; TempCo: 25 ppm/C; SizeArea_mm2: 1.28; SizeX_mm: 1.6; SizeY_mm: 0.8; SizeZ_mm: 1; EIA_Code: E192; U/M: EA; AEC Category: Q200
signal-integrity model Resistor
simulation model Resistor
footprint 0603
footprint 0603M
footprint 0603L
footprint 0603_HV
footprint 0603S
pins: 1, 2

## RT0603BRD07796RL
designator R?  ValueDisplayed: 796  (hidden comment: RT0603BRD07796RL)
RES, 796, 0.1%, 0.1 W, 0603; Manufacturer: Yageo America; CompType: Resistor; Value: 796; Value_Code: 796R; Tolerance_%: 0.1; Value2: 0.1W; VDC_V: 75; TempCo: 25 ppm/C; SizeArea_mm2: 1.28; SizeX_mm: 1.6; SizeY_mm: 0.8; SizeZ_mm: 1; EIA_Code: E192; U/M: EA; AEC Category: Q200
signal-integrity model Resistor
simulation model Resistor
footprint 0603
footprint 0603M
footprint 0603L
footprint 0603_HV
footprint 0603S
pins: 1, 2

## RT0603BRD07806RL
designator R?  ValueDisplayed: 806  (hidden comment: RT0603BRD07806RL)
RES, 806, 0.1%, 0.1 W, 0603; Manufacturer: Yageo America; CompType: Resistor; Value: 806; Value_Code: 806R; Tolerance_%: 0.1; Value2: 0.1W; VDC_V: 75; TempCo: 25 ppm/C; SizeArea_mm2: 1.28; SizeX_mm: 1.6; SizeY_mm: 0.8; SizeZ_mm: 1; EIA_Code: E192; U/M: EA; AEC Category: Q200
signal-integrity model Resistor
simulation model Resistor
footprint 0603
footprint 0603M
footprint 0603L
footprint 0603_HV
footprint 0603S
pins: 1, 2

## RT0603BRD07816RL
designator R?  ValueDisplayed: 816  (hidden comment: RT0603BRD07816RL)
RES, 816, 0.1%, 0.1 W, 0603; Manufacturer: Yageo America; CompType: Resistor; Value: 816; Value_Code: 816R; Tolerance_%: 0.1; Value2: 0.1W; VDC_V: 75; TempCo: 25 ppm/C; SizeArea_mm2: 1.28; SizeX_mm: 1.6; SizeY_mm: 0.8; SizeZ_mm: 1; EIA_Code: E192; U/M: EA; AEC Category: Q200
signal-integrity model Resistor
simulation model Resistor
footprint 0603
footprint 0603M
footprint 0603L
footprint 0603_HV
footprint 0603S
pins: 1, 2

## RT0603BRD07825RL
designator R?  ValueDisplayed: 825  (hidden comment: RT0603BRD07825RL)
RES, 825, 0.1%, 0.1 W, 0603; Manufacturer: Yageo America; CompType: Resistor; Value: 825; Value_Code: 825R; Tolerance_%: 0.1; Value2: 0.1W; VDC_V: 75; TempCo: 25 ppm/C; SizeArea_mm2: 1.28; SizeX_mm: 1.6; SizeY_mm: 0.8; SizeZ_mm: 1; EIA_Code: E192; U/M: EA; AEC Category: Q200
signal-integrity model Resistor
simulation model Resistor
footprint 0603
footprint 0603M
footprint 0603L
footprint 0603_HV
footprint 0603S
pins: 1, 2

## RT0603BRD07835RL
designator R?  ValueDisplayed: 835  (hidden comment: RT0603BRD07835RL)
RES, 835, 0.1%, 0.1 W, 0603; Manufacturer: Yageo America; CompType: Resistor; Value: 835; Value_Code: 835R; Tolerance_%: 0.1; Value2: 0.1W; VDC_V: 75; TempCo: 25 ppm/C; SizeArea_mm2: 1.28; SizeX_mm: 1.6; SizeY_mm: 0.8; SizeZ_mm: 1; EIA_Code: E192; U/M: EA; AEC Category: Q200
signal-integrity model Resistor
simulation model Resistor
footprint 0603
footprint 0603M
footprint 0603L
footprint 0603_HV
footprint 0603S
pins: 1, 2

## RT0603BRD07845RL
designator R?  ValueDisplayed: 845  (hidden comment: RT0603BRD07845RL)
RES, 845, 0.1%, 0.1 W, 0603; Manufacturer: Yageo America; CompType: Resistor; Value: 845; Value_Code: 845R; Tolerance_%: 0.1; Value2: 0.1W; VDC_V: 75; TempCo: 25 ppm/C; SizeArea_mm2: 1.28; SizeX_mm: 1.6; SizeY_mm: 0.8; SizeZ_mm: 1; EIA_Code: E192; U/M: EA; AEC Category: Q200
signal-integrity model Resistor
simulation model Resistor
footprint 0603
footprint 0603M
footprint 0603L
footprint 0603_HV
footprint 0603S
pins: 1, 2

## RT0603BRD07856RL
designator R?  ValueDisplayed: 856  (hidden comment: RT0603BRD07856RL)
RES, 856, 0.1%, 0.1 W, 0603; Manufacturer: Yageo America; CompType: Resistor; Value: 856; Value_Code: 856R; Tolerance_%: 0.1; Value2: 0.1W; VDC_V: 75; TempCo: 25 ppm/C; SizeArea_mm2: 1.28; SizeX_mm: 1.6; SizeY_mm: 0.8; SizeZ_mm: 1; EIA_Code: E192; U/M: EA; AEC Category: Q200
signal-integrity model Resistor
simulation model Resistor
footprint 0603
footprint 0603M
footprint 0603L
footprint 0603_HV
footprint 0603S
pins: 1, 2

## RT0603BRD07866RL
designator R?  ValueDisplayed: 866  (hidden comment: RT0603BRD07866RL)
RES, 866, 0.1%, 0.1 W, 0603; Manufacturer: Yageo America; CompType: Resistor; Value: 866; Value_Code: 866R; Tolerance_%: 0.1; Value2: 0.1W; VDC_V: 75; TempCo: 25 ppm/C; SizeArea_mm2: 1.28; SizeX_mm: 1.6; SizeY_mm: 0.8; SizeZ_mm: 1; EIA_Code: E192; U/M: EA; AEC Category: Q200
signal-integrity model Resistor
simulation model Resistor
footprint 0603
footprint 0603M
footprint 0603L
footprint 0603_HV
footprint 0603S
pins: 1, 2

## RT0603BRD07876RL
designator R?  ValueDisplayed: 876  (hidden comment: RT0603BRD07876RL)
RES, 876, 0.1%, 0.1 W, 0603; Manufacturer: Yageo America; CompType: Resistor; Value: 876; Value_Code: 876R; Tolerance_%: 0.1; Value2: 0.1W; VDC_V: 75; TempCo: 25 ppm/C; SizeArea_mm2: 1.28; SizeX_mm: 1.6; SizeY_mm: 0.8; SizeZ_mm: 1; EIA_Code: E192; U/M: EA; AEC Category: Q200
signal-integrity model Resistor
simulation model Resistor
footprint 0603
footprint 0603M
footprint 0603L
footprint 0603_HV
footprint 0603S
pins: 1, 2

## RT0603BRD07887RL
designator R?  ValueDisplayed: 887  (hidden comment: RT0603BRD07887RL)
RES, 887, 0.1%, 0.1 W, 0603; Manufacturer: Yageo America; CompType: Resistor; Value: 887; Value_Code: 887R; Tolerance_%: 0.1; Value2: 0.1W; VDC_V: 75; TempCo: 25 ppm/C; SizeArea_mm2: 1.28; SizeX_mm: 1.6; SizeY_mm: 0.8; SizeZ_mm: 1; EIA_Code: E192; U/M: EA; AEC Category: Q200
signal-integrity model Resistor
simulation model Resistor
footprint 0603
footprint 0603M
footprint 0603L
footprint 0603_HV
footprint 0603S
pins: 1, 2

## RT0603BRD07898RL
designator R?  ValueDisplayed: 898  (hidden comment: RT0603BRD07898RL)
RES, 898, 0.1%, 0.1 W, 0603; Manufacturer: Yageo America; CompType: Resistor; Value: 898; Value_Code: 898R; Tolerance_%: 0.1; Value2: 0.1W; VDC_V: 75; TempCo: 25 ppm/C; SizeArea_mm2: 1.28; SizeX_mm: 1.6; SizeY_mm: 0.8; SizeZ_mm: 1; EIA_Code: E192; U/M: EA; AEC Category: Q200
signal-integrity model Resistor
simulation model Resistor
footprint 0603
footprint 0603M
footprint 0603L
footprint 0603_HV
footprint 0603S
pins: 1, 2

## RT0603BRD07909RL
designator R?  ValueDisplayed: 909  (hidden comment: RT0603BRD07909RL)
RES, 909, 0.1%, 0.1 W, 0603; Manufacturer: Yageo America; CompType: Resistor; Value: 909; Value_Code: 909R; Tolerance_%: 0.1; Value2: 0.1W; VDC_V: 75; TempCo: 25 ppm/C; SizeArea_mm2: 1.28; SizeX_mm: 1.6; SizeY_mm: 0.8; SizeZ_mm: 1; EIA_Code: E192; U/M: EA; AEC Category: Q200
signal-integrity model Resistor
simulation model Resistor
footprint 0603
footprint 0603M
footprint 0603L
footprint 0603_HV
footprint 0603S
pins: 1, 2

## RT0603BRD07920RL
designator R?  ValueDisplayed: 920  (hidden comment: RT0603BRD07920RL)
RES, 920, 0.1%, 0.1 W, 0603; Manufacturer: Yageo America; CompType: Resistor; Value: 920; Value_Code: 920R; Tolerance_%: 0.1; Value2: 0.1W; VDC_V: 75; TempCo: 25 ppm/C; SizeArea_mm2: 1.28; SizeX_mm: 1.6; SizeY_mm: 0.8; SizeZ_mm: 1; EIA_Code: E192; U/M: EA; AEC Category: Q200
signal-integrity model Resistor
simulation model Resistor
footprint 0603
footprint 0603M
footprint 0603L
footprint 0603_HV
footprint 0603S
pins: 1, 2

## RT0603BRD07931RL
designator R?  ValueDisplayed: 931  (hidden comment: RT0603BRD07931RL)
RES, 931, 0.1%, 0.1 W, 0603; Manufacturer: Yageo America; CompType: Resistor; Value: 931; Value_Code: 931R; Tolerance_%: 0.1; Value2: 0.1W; VDC_V: 75; TempCo: 25 ppm/C; SizeArea_mm2: 1.28; SizeX_mm: 1.6; SizeY_mm: 0.8; SizeZ_mm: 1; EIA_Code: E192; U/M: EA; AEC Category: Q200
signal-integrity model Resistor
simulation model Resistor
footprint 0603
footprint 0603M
footprint 0603L
footprint 0603_HV
footprint 0603S
pins: 1, 2

## RT0603BRD07942RL
designator R?  ValueDisplayed: 942  (hidden comment: RT0603BRD07942RL)
RES, 942, 0.1%, 0.1 W, 0603; Manufacturer: Yageo America; CompType: Resistor; Value: 942; Value_Code: 942R; Tolerance_%: 0.1; Value2: 0.1W; VDC_V: 75; TempCo: 25 ppm/C; SizeArea_mm2: 1.28; SizeX_mm: 1.6; SizeY_mm: 0.8; SizeZ_mm: 1; EIA_Code: E192; U/M: EA; AEC Category: Q200
signal-integrity model Resistor
simulation model Resistor
footprint 0603
footprint 0603M
footprint 0603L
footprint 0603_HV
footprint 0603S
pins: 1, 2

## RT0603BRD07953RL
designator R?  ValueDisplayed: 953  (hidden comment: RT0603BRD07953RL)
RES, 953, 0.1%, 0.1 W, 0603; Manufacturer: Yageo America; CompType: Resistor; Value: 953; Value_Code: 953R; Tolerance_%: 0.1; Value2: 0.1W; VDC_V: 75; TempCo: 25 ppm/C; SizeArea_mm2: 1.28; SizeX_mm: 1.6; SizeY_mm: 0.8; SizeZ_mm: 1; EIA_Code: E192; U/M: EA; AEC Category: Q200
signal-integrity model Resistor
simulation model Resistor
footprint 0603
footprint 0603M
footprint 0603L
footprint 0603_HV
footprint 0603S
pins: 1, 2

## RT0603BRD07965RL
designator R?  ValueDisplayed: 965  (hidden comment: RT0603BRD07965RL)
RES, 965, 0.1%, 0.1 W, 0603; Manufacturer: Yageo America; CompType: Resistor; Value: 965; Value_Code: 965R; Tolerance_%: 0.1; Value2: 0.1W; VDC_V: 75; TempCo: 25 ppm/C; SizeArea_mm2: 1.28; SizeX_mm: 1.6; SizeY_mm: 0.8; SizeZ_mm: 1; EIA_Code: E192; U/M: EA; AEC Category: Q200
signal-integrity model Resistor
simulation model Resistor
footprint 0603
footprint 0603M
footprint 0603L
footprint 0603_HV
footprint 0603S
pins: 1, 2

## RT0603BRD07976RL
designator R?  ValueDisplayed: 976  (hidden comment: RT0603BRD07976RL)
RES, 976, 0.1%, 0.1 W, 0603; Manufacturer: Yageo America; CompType: Resistor; Value: 976; Value_Code: 976R; Tolerance_%: 0.1; Value2: 0.1W; VDC_V: 75; TempCo: 25 ppm/C; SizeArea_mm2: 1.28; SizeX_mm: 1.6; SizeY_mm: 0.8; SizeZ_mm: 1; EIA_Code: E192; U/M: EA; AEC Category: Q200
signal-integrity model Resistor
simulation model Resistor
footprint 0603
footprint 0603M
footprint 0603L
footprint 0603_HV
footprint 0603S
pins: 1, 2

## RT0603BRD07988RL
designator R?  ValueDisplayed: 988  (hidden comment: RT0603BRD07988RL)
RES, 988, 0.1%, 0.1 W, 0603; Manufacturer: Yageo America; CompType: Resistor; Value: 988; Value_Code: 988R; Tolerance_%: 0.1; Value2: 0.1W; VDC_V: 75; TempCo: 25 ppm/C; SizeArea_mm2: 1.28; SizeX_mm: 1.6; SizeY_mm: 0.8; SizeZ_mm: 1; EIA_Code: E192; U/M: EA; AEC Category: Q200
signal-integrity model Resistor
simulation model Resistor
footprint 0603
footprint 0603M
footprint 0603L
footprint 0603_HV
footprint 0603S
pins: 1, 2

## RT0603DRD073K09L
designator R?  ValueDisplayed: 3.09k  (hidden comment: RT0603DRD073K09L)
RES, 3.09 k, 0.5%, 0.1 W, 0603; Manufacturer: Yageo America; CompType: Resistor; Value: 3.09k; Res_ohm: 3090; Value_Code: 3k09; Tolerance_%: 0.5; Power_W: 0.1; Value2: 0.1W; VDC_V: 75; TempCo: 25 ppm/C; SizeArea_mm2: 1.28; SizeX_mm: 1.6; SizeY_mm: 0.8; SizeZ_mm: 1; EIA_Code: E192; U/M: EA; AEC Category: Q200
signal-integrity model Resistor
simulation model Resistor
footprint 0603
footprint 0603M
footprint 0603L
footprint 0603_HV
footprint 0603S
pins: 1, 2

## RT0603DRD0727KL
designator R?  ValueDisplayed: 27.0k  (hidden comment: RT0603DRD0727KL)
RES, 27.0 k, 0.5%, 0.1 W, 0603; Manufacturer: Yageo America; CompType: Resistor; Value: 27.0k; Res_ohm: 27000; Value_Code: 27k0; Tolerance_%: 0.5; Power_W: 0.1; Value2: 0.1W; VDC_V: 75; TempCo: 25 ppm/C; SizeArea_mm2: 1.28; SizeX_mm: 1.6; SizeY_mm: 0.8; SizeZ_mm: 1; U/M: EA; AEC Category: Q200
signal-integrity model Resistor
simulation model Resistor
footprint 0603
footprint 0603M
footprint 0603L
footprint 0603_HV
footprint 0603S
pins: 1, 2

## RT0603DRD0743K2L
designator R?  ValueDisplayed: 43.2k  (hidden comment: RT0603DRD0743K2L)
RES, 43.2 k, 0.5%, 0.1 W, 0603; Manufacturer: Yageo America; CompType: Resistor; Value: 43.2k; Res_ohm: 43200; Value_Code: 43k2; Tolerance_%: 0.5; Power_W: 0.1; Value2: 0.1W; VDC_V: 75; TempCo: 25 ppm/C; SizeArea_mm2: 1.28; SizeX_mm: 1.6; SizeY_mm: 0.8; SizeZ_mm: 1; EIA_Code: E192; U/M: EA; AEC Category: Q200
signal-integrity model Resistor
simulation model Resistor
footprint 0603
footprint 0603M
footprint 0603L
footprint 0603_HV
footprint 0603S
pins: 1, 2

## RT0603DRD07165KL
designator R?  ValueDisplayed: 165k  (hidden comment: RT0603DRD07165KL)
RES, 165 k, 0.5%, 0.1 W, 0603; Manufacturer: Yageo America; CompType: Resistor; Value: 165k; Res_ohm: 165000; Tolerance_%: 0.5; Power_W: 0.1; Value2: 0.1W; VDC_V: 75; TempCo: 25 ppm/C; SizeArea_mm2: 1.28; SizeX_mm: 1.6; SizeY_mm: 0.8; SizeZ_mm: 1; EIA_Code: E192; U/M: EA; AEC Category: Q200
signal-integrity model Resistor
simulation model Resistor
footprint 0603
footprint 0603M
footprint 0603L
footprint 0603_HV
footprint 0603S
pins: 1, 2

## RT0603DRE071K01L
designator R?  ValueDisplayed: 1.01k  (hidden comment: RT0603DRE071K01L)
RES, 1.01 k, 0.5%, 0.1 W, 0603; Manufacturer: Yageo America; CompType: Resistor; Value: 1.01k; Res_ohm: 1010; Value_Code: 1k01; Tolerance_%: 0.5; Power_W: 0.1; Value2: 0.1W; VDC_V: 75; TempCo: 50 ppm/C; SizeArea_mm2: 1.28; SizeX_mm: 1.6; SizeY_mm: 0.8; SizeZ_mm: 1; EIA_Code: E192; U/M: EA; AEC Category: Q200
signal-integrity model Resistor
simulation model Resistor
footprint 0603
footprint 0603M
footprint 0603L
footprint 0603_HV
footprint 0603S
pins: 1, 2

## RT0603DRE071K1L
designator R?  ValueDisplayed: 1.10k  (hidden comment: RT0603DRE071K1L)
RES, 1.10 k, 0.5%, 0.1 W, 0603; Manufacturer: Yageo America; CompType: Resistor; Value: 1.10k; Res_ohm: 1100; Value_Code: 1k10; Tolerance_%: 0.5; Power_W: 0.1; Value2: 0.1W; VDC_V: 75; TempCo: 50 ppm/C; SizeArea_mm2: 1.28; SizeX_mm: 1.6; SizeY_mm: 0.8; SizeZ_mm: 1; EIA_Code: E192; U/M: EA; AEC Category: Q200
signal-integrity model Resistor
simulation model Resistor
footprint 0603
footprint 0603M
footprint 0603L
footprint 0603_HV
footprint 0603S
pins: 1, 2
